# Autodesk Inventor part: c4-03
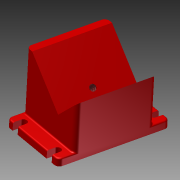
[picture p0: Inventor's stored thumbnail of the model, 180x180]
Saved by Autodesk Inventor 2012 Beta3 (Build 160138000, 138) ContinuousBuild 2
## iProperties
Created: 2010-11
Part Number: c4-03
Material: Default
Document SubType Name: Modeling
Designer: Beta-8540w
Density: 1 g/cm^3
Author: Beta-8540w
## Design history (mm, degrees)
sketch "Sketch1"
  geometry: L1 (-45, 0)-(45, 0); L2 (45, 0)-(45, 10); L3 (45, 10)-(-45, 10); L4 (-45, 10)-(-45, 0); L5 (-45, 10)-(-45, 90); L6 (-45, 90)-(-35, 90); L7 (-35, 90)-(14.497, 40.503); L8 (14.497, 40.503)-(45, 71.005); L9 (45, 71.005)-(45, 10); 2 further points
  constraints: 18 end point, 4 perpendicular, 3 collinear, 2 parallel, 2 point on line, 1 coincident, 1 horizontal, 1 midpoint
  dimensions: "d0" = 90 distance of L3.end L2.end; "d1" = 10 distance of L2.end L1.end; "d2" = 80 distance of L5.start L5.end; "d3" = 10 distance of L5.end L6.end; "d4" = 70 distance of L6.end L7.end; "d5" = 135 deg angle of L6 L7
extrude "Extrusion1" new body sketch "Sketch1" stored distance "d8" = 100; taper "d9" = 0 deg
extrude "Extrusion2" join sketch "Sketch1" stored distance "d10" = 140; taper "d11" = 0 deg
fillet "Fillet1" dims "d12" = 6
fillet "Fillet2" dims "d13" = 2
sketch "Sketch2"
  geometry: L1 (78, -2)-(0, -2) reference; L2 (-6, 4)-(-6, 132) reference; L3 (4.5, -2)-(13.5, -2); L4 (13.5, -2)-(13.5, 8); L5 (13.5, 8)-(4.5, 8); L6 (4.5, 8)-(4.5, -2); 2 further points
  constraints: 8 end point, 2 parallel, 1 horizontal, 1 horizontal alignment, 1 midpoint, 1 perpendicular, 1 point on line, 2 other
  dimensions: "d14" = 9 distance of L5.end L4.end; "d15" = 10 distance of L4.end L3.end; "d16" = 15 distance from line of point (9, 8) L2
extrude "Extrusion3" cut sketch "Sketch2" stored distance "d17" = 140; taper "d18" = 0 deg
mirror "Mirror1"
mirror "Mirror2"
hole "Hole1" diameter "d21" = 8.376; stored, may be unused: countersink angle "d25" = 90 deg, drill point angle "d27" = 118 deg; dims "d19" = 50, "d20" = 14, "d22" = 30, "d23" = 4, "d24" = 2, "d26" = 33
body "Solid1"
